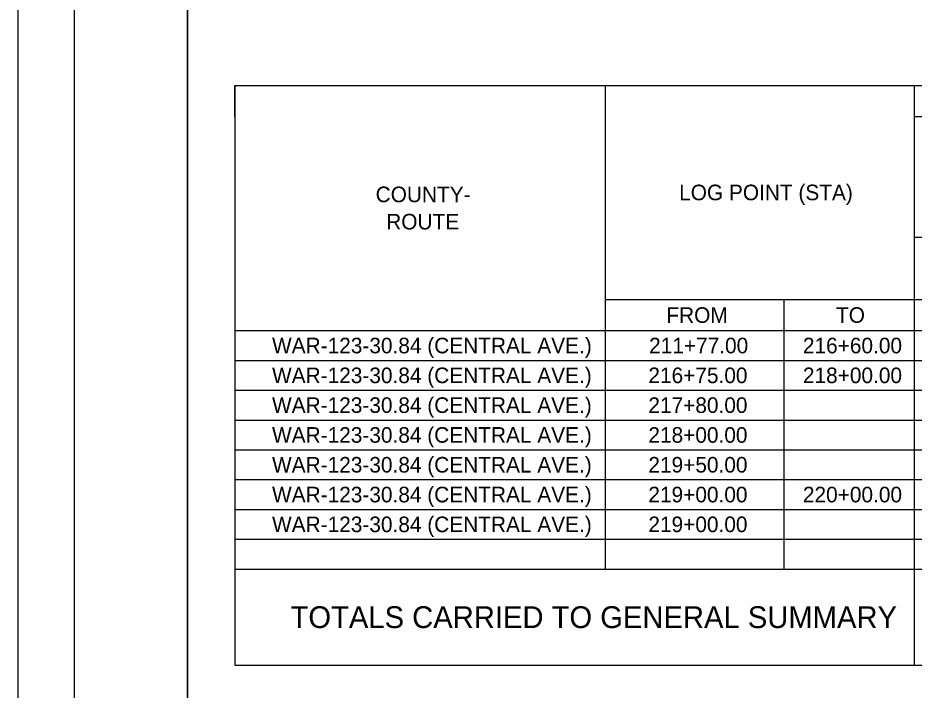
# Model space of a CAD drawing. Extents: x 0 to 53.1, y -5.3 to 22.
# Drawn here: x 0 to 7.93, y 10.09 to 16.05 of the extents above; entities that cross this region are included whole.
import ezdxf

# ---------------------------------------------------------------- set-up
doc = ezdxf.new("R2010")
doc.units = 0
for name, color, linetype in [('SH_Border', 7, 'Continuous'), ('SH_Cut_Line', 7, 'Continuous'), ('SH_Text', 7, 'Continuous')]:
    doc.layers.add(name, color=color, linetype=linetype)

msp = doc.modelspace()

# ---------------------------------------------------------------- linework, layer by layer
at = {"layer": 'SH_Border'}
for points in [[(0.5, 21.5), (1.5, 21.5), (1.5, 0.5), (0.5, 0.5)], [(1.5, 21.5), (33.5, 21.5), (33.5, 0.5), (1.5, 0.5)]]:
    msp.add_lwpolyline(points, close=True, dxfattribs=at)
at = {"layer": 'SH_Cut_Line'}
msp.add_lwpolyline([(0, 0), (34, 0), (34, 22), (0, 22)], close=True, dxfattribs=at)
at = {"layer": 'SH_Text'}
for p, q in [((1.9215, 15.4482), (7.9335, 15.4482)), ((1.9215, 15.4482), (1.9215, 15.1722)), ((5.1975, 15.4482), (5.1975, 15.1722)), ((7.9335, 15.4482), (27.6855, 15.4482)), ((7.9335, 15.4482), (7.9335, 15.1722)), ((1.9215, 15.1722), (1.9215, 14.6562)), ((5.1975, 15.1722), (5.1975, 14.6562)), ((7.9335, 15.1722), (27.6855, 15.1722)), ((7.9335, 15.1722), (7.9335, 14.6562)), ((1.9215, 14.6562), (1.9215, 14.3802)), ((5.1975, 14.6562), (5.1975, 14.3802)), ((7.9335, 14.6562), (7.9335, 14.3802)), ((1.9215, 14.3802), (1.9215, 14.1042)), ((5.1975, 14.3802), (5.1975, 14.1042)), ((7.9335, 14.3802), (7.9335, 14.1042)), ((1.9215, 14.1042), (1.9215, 13.8282)), ((5.1975, 14.1042), (5.1975, 13.8282)), ((7.9335, 14.1042), (9.0735, 14.1042)), ((7.9335, 14.1042), (7.9335, 13.8282)), ((1.9215, 13.8282), (1.9215, 13.5522)), ((5.1975, 13.8282), (5.1975, 13.5522)), ((7.9335, 13.8282), (7.9335, 13.5522)), ((1.9215, 13.5522), (1.9215, 12.7482)), ((5.1975, 13.5522), (7.9335, 13.5522)), ((5.1975, 13.5522), (5.1975, 12.7482)), ((6.7815, 13.5522), (6.7815, 12.7482)), ((7.9335, 13.5522), (27.6855, 13.5522)), ((7.9335, 13.5522), (7.9335, 12.7482)), ((1.9215, 13.2762), (7.9335, 13.2762)), ((7.9335, 13.2762), (27.6855, 13.2762)), ((1.9215, 13.0122), (7.9335, 13.0122)), ((7.9335, 13.0122), (27.6855, 13.0122)), ((1.9215, 12.7482), (7.9335, 12.7482)), ((1.9215, 12.7482), (1.9215, 12.4842)), ((5.1975, 12.7482), (5.1975, 12.4842)), ((6.7815, 12.7482), (6.7815, 12.4842)), ((7.9335, 12.7482), (27.6855, 12.7482)), ((7.9335, 12.7482), (7.9335, 12.4842)), ((1.9215, 12.4842), (7.9335, 12.4842)), ((1.9215, 12.4842), (1.9215, 12.2202)), ((5.1975, 12.4842), (5.1975, 12.2202)), ((6.7815, 12.4842), (6.7815, 12.2202)), ((7.9335, 12.4842), (27.6855, 12.4842)), ((7.9335, 12.4842), (7.9335, 12.2202)), ((1.9215, 12.2202), (7.9335, 12.2202)), ((1.9215, 12.2202), (1.9215, 11.9562)), ((5.1975, 12.2202), (5.1975, 11.9562)), ((6.7815, 12.2202), (6.7815, 11.9562)), ((7.9335, 12.2202), (27.6855, 12.2202)), ((7.9335, 12.2202), (7.9335, 11.9562)), ((1.9215, 11.9562), (7.9335, 11.9562)), ((1.9215, 11.9562), (1.9215, 10.3122)), ((5.1975, 11.9562), (5.1975, 11.1642)), ((6.7815, 11.9562), (6.7815, 11.1642)), ((7.9335, 11.9562), (27.6855, 11.9562)), ((7.9335, 11.9562), (7.9335, 10.3122)), ((1.9215, 11.6922), (7.9335, 11.6922)), ((7.9335, 11.6922), (27.6855, 11.6922)), ((1.9215, 11.4282), (7.9335, 11.4282)), ((7.9335, 11.4282), (27.6855, 11.4282)), ((1.9215, 11.1642), (7.9335, 11.1642)), ((7.9335, 11.1642), (27.6855, 11.1642)), ((1.9215, 10.3122), (7.9335, 10.3122)), ((7.9335, 10.3122), (27.6855, 10.3122))]:
    msp.add_line(p, q, dxfattribs=at)
for points in [[(1.9215, 15.4482), (1.9215, 15.4482), (1.9215, 15.4482), (1.9215, 15.4482)], [(1.9215, 15.4482), (1.9215, 15.4482), (1.9215, 15.4482), (1.9215, 15.4482)], [(1.9215, 15.4482), (1.9215, 15.4482), (1.9215, 15.4482), (1.9215, 15.4482)], [(1.9215, 15.4482), (1.9215, 15.4482), (1.9215, 15.1722), (1.9215, 15.1722)], [(1.9215, 15.4482), (1.9215, 15.4482), (1.9215, 15.1722), (1.9215, 15.1722)], [(1.9215, 15.4482), (1.9215, 15.4482), (1.9215, 15.1722), (1.9215, 15.1722)], [(1.9215, 15.4482), (1.9215, 15.4482), (1.9215, 15.1842), (1.9215, 15.1842)], [(1.9215, 15.4482), (1.9215, 15.4482), (1.9215, 15.1842), (1.9215, 15.1842)], [(1.9215, 15.4482), (1.9215, 15.4482), (1.9215, 15.1842), (1.9215, 15.1842)], [(1.9215, 15.4482), (1.9215, 15.4482), (1.9215, 15.1842), (1.9215, 15.1842)], [(1.9215, 15.4482), (1.9215, 15.4482), (1.9215, 15.1842), (1.9215, 15.1842)], [(1.9215, 15.4482), (1.9215, 15.4482), (1.9215, 15.1842), (1.9215, 15.1842)], [(1.9215, 15.4482), (1.9215, 15.4482), (1.9215, 15.1842), (1.9215, 15.1842)], [(1.9215, 15.4482), (1.9215, 15.4482), (1.9215, 15.1842), (1.9215, 15.1842)], [(1.9215, 15.4482), (1.9215, 15.4482), (1.9215, 15.1842), (1.9215, 15.1842)], [(1.9215, 15.4482), (1.9215, 15.4482), (1.9215, 15.1842), (1.9215, 15.1842)], [(1.9215, 15.4482), (1.9215, 15.4482), (1.9215, 15.1842), (1.9215, 15.1842)], [(1.9215, 15.4482), (1.9215, 15.4482), (1.9215, 15.1842), (1.9215, 15.1842)], [(1.9215, 15.4482), (1.9215, 15.4482), (1.9215, 15.1842), (1.9215, 15.1842)], [(1.9215, 15.4482), (1.9215, 15.4482), (1.9215, 15.1842), (1.9215, 15.1842)], [(1.9215, 15.4482), (1.9215, 15.4482), (1.9215, 15.1842), (1.9215, 15.1842)], [(1.9215, 15.4482), (1.9215, 15.4482), (1.9215, 15.1842), (1.9215, 15.1842)], [(1.9215, 15.4482), (1.9215, 15.4482), (1.9215, 15.4482), (1.9215, 15.4482)], [(1.9215, 15.4482), (1.9215, 15.4482), (1.9215, 15.4482), (1.9215, 15.4482)]]:
    msp.add_lwpolyline(points, close=True, dxfattribs=at)

# ---------------------------------------------------------------- texts
for s, height, p in [('COUNTY-', 0.138, (3.1669, 14.414)), ('LOG POINT (STA)', 0.138, (5.8535, 14.4312)), ('ROUTE', 0.138, (3.2604, 14.1725)), ('FROM', 0.138, (5.7405, 13.3452)), ('TO', 0.138, (7.2424, 13.3452)), ('WAR-123-30.84 (CENTRAL AVE.)', 0.138, (2.2496, 13.0752)), ('211+77.00', 0.138, (5.5877, 13.0752)), ('216+60.00', 0.138, (6.9493, 13.0752)), ('WAR-123-30.84 (CENTRAL AVE.)', 0.138, (2.2496, 12.8112)), ('216+75.00', 0.138, (5.5813, 12.8112)), ('218+00.00', 0.138, (6.9493, 12.8112)), ('WAR-123-30.84 (CENTRAL AVE.)', 0.138, (2.2496, 12.5472)), ('217+80.00', 0.138, (5.5813, 12.5472)), ('WAR-123-30.84 (CENTRAL AVE.)', 0.138, (2.2496, 12.2832)), ('218+00.00', 0.138, (5.5813, 12.2832)), ('WAR-123-30.84 (CENTRAL AVE.)', 0.138, (2.2496, 12.0192)), ('219+50.00', 0.138, (5.5813, 12.0192)), ('WAR-123-30.84 (CENTRAL AVE.)', 0.138, (2.2496, 11.7552)), ('219+00.00', 0.138, (5.5813, 11.7552)), ('220+00.00', 0.138, (6.9493, 11.7552)), ('WAR-123-30.84 (CENTRAL AVE.)', 0.138, (2.2496, 11.4912)), ('219+00.00', 0.138, (5.5813, 11.4912)), ('TOTALS CARRIED TO GENERAL SUMMARY', 0.1932, (2.4134, 10.6416))]:
    msp.add_text(s, height=height, dxfattribs=at).set_placement(p)

doc.saveas('drawing.dxf')
